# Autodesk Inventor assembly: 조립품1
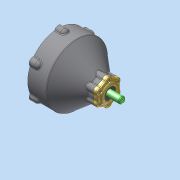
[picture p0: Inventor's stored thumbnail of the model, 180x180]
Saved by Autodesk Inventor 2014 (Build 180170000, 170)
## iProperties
Created: 2026-05
Part Number: 조립품1
Document SubType Name: Assembly
Designer: dg
Author: dg
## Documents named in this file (19)
- C:\Users\dg\Desktop\760503V1001\조립품1.iam
- C:\Users\dg\Desktop\760503V1001\부품2.ipt
- C:\Users\dg\Desktop\760503V1001\가져온 구성요소\선 기어 축\선 기어 축.ipt
- C:\Users\dg\Desktop\760503V1001\가져온 구성요소\깊은 홈 볼 베어링 6203\깊은 홈 볼 베어링 6203.ipt
- C:\Users\dg\Desktop\760503V1001\가져온 구성요소\축용 C형 멈춤링 17\축용 C형 멈춤링 17.ipt
- C:\Users\dg\Desktop\760503V1001\가져온 구성요소\유성 캐리어\유성 캐리어.ipt
- C:\Users\dg\Desktop\760503V1001\가져온 구성요소\유성 기어\유성 기어.ipt
- C:\Users\dg\Desktop\760503V1001\가져온 구성요소\깊은 홈 볼 베어링 6900\깊은 홈 볼 베어링 6900.ipt
- C:\Users\dg\Desktop\760503V1001\가져온 구성요소\엔드 캡\엔드 캡.ipt
- C:\Users\dg\Desktop\760503V1001\가져온 구성요소\6각 구멍붙이 볼트 M4x10\6각 구멍붙이 볼트 M4x10.ipt
- C:\Users\dg\Desktop\760503V1001\가져온 구성요소\유성 축\유성 축.ipt
- C:\Users\dg\Desktop\760503V1001\가져온 구성요소\링 기어\링 기어.ipt
- C:\Users\dg\Desktop\760503V1001\가져온 구성요소\칼라\칼라.ipt
- C:\Users\dg\Desktop\760503V1001\가져온 구성요소\유성 캐리어 커버\유성 캐리어 커버.ipt
- C:\Users\dg\Desktop\760503V1001\가져온 구성요소\깊은 홈 볼 베어링 6010\깊은 홈 볼 베어링 6010.ipt
- C:\Users\dg\Desktop\760503V1001\가져온 구성요소\커버\커버.ipt
- C:\Users\dg\Desktop\760503V1001\가져온 구성요소\오일 실 17 32 8\오일 실 17 32 8.ipt
- C:\Users\dg\Desktop\760503V1001\가져온 구성요소\6각 구멍붙이 볼트 M4x20\6각 구멍붙이 볼트 M4x20.ipt
- C:\Users\dg\Desktop\760503V1001\가져온 구성요소\6각 구멍붙이 볼트 M6x10\6각 구멍붙이 볼트 M6x10.ipt
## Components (19 placed, 3 different names)
1. 6각 구멍붙이 볼트 M4x10:1
2. 6각 구멍붙이 볼트 M4x10:2
3. 6각 구멍붙이 볼트 M4x10:3
4. 6각 구멍붙이 볼트 M4x10:4
5. 6각 구멍붙이 볼트 M4x10:5
6. 6각 구멍붙이 볼트 M4x10:6
7. 6각 구멍붙이 볼트 M4x10:7
8. 6각 구멍붙이 볼트 M4x10:8
9. 6각 구멍붙이 볼트 M4x10:9
10. 6각 구멍붙이 볼트 M4x20:1
11. 6각 구멍붙이 볼트 M4x20:2
12. 6각 구멍붙이 볼트 M4x20:3
13. 6각 구멍붙이 볼트 M4x20:4
14. 6각 구멍붙이 볼트 M4x20:5
15. 6각 구멍붙이 볼트 M4x20:6
16. 6각 구멍붙이 볼트 M6x10:1
17. 6각 구멍붙이 볼트 M6x10:2
18. 6각 구멍붙이 볼트 M6x10:3
19. 6각 구멍붙이 볼트 M6x10:4
